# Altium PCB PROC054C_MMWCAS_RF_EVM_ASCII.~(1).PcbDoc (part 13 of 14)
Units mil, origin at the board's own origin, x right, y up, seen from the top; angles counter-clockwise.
Board outline 6299.21 x 5370.07 mil, 8 copper layers (L1 TOP, L2 GND, L3 SIGNAL 1, L4 GND, L5 SIGNAL 2, L6 SIGNAL 3, L7 GND, L8 BOTTOM), stack 53.5 mil thick; 775 components, 552 nets, 2648 pads, 7845 vias.
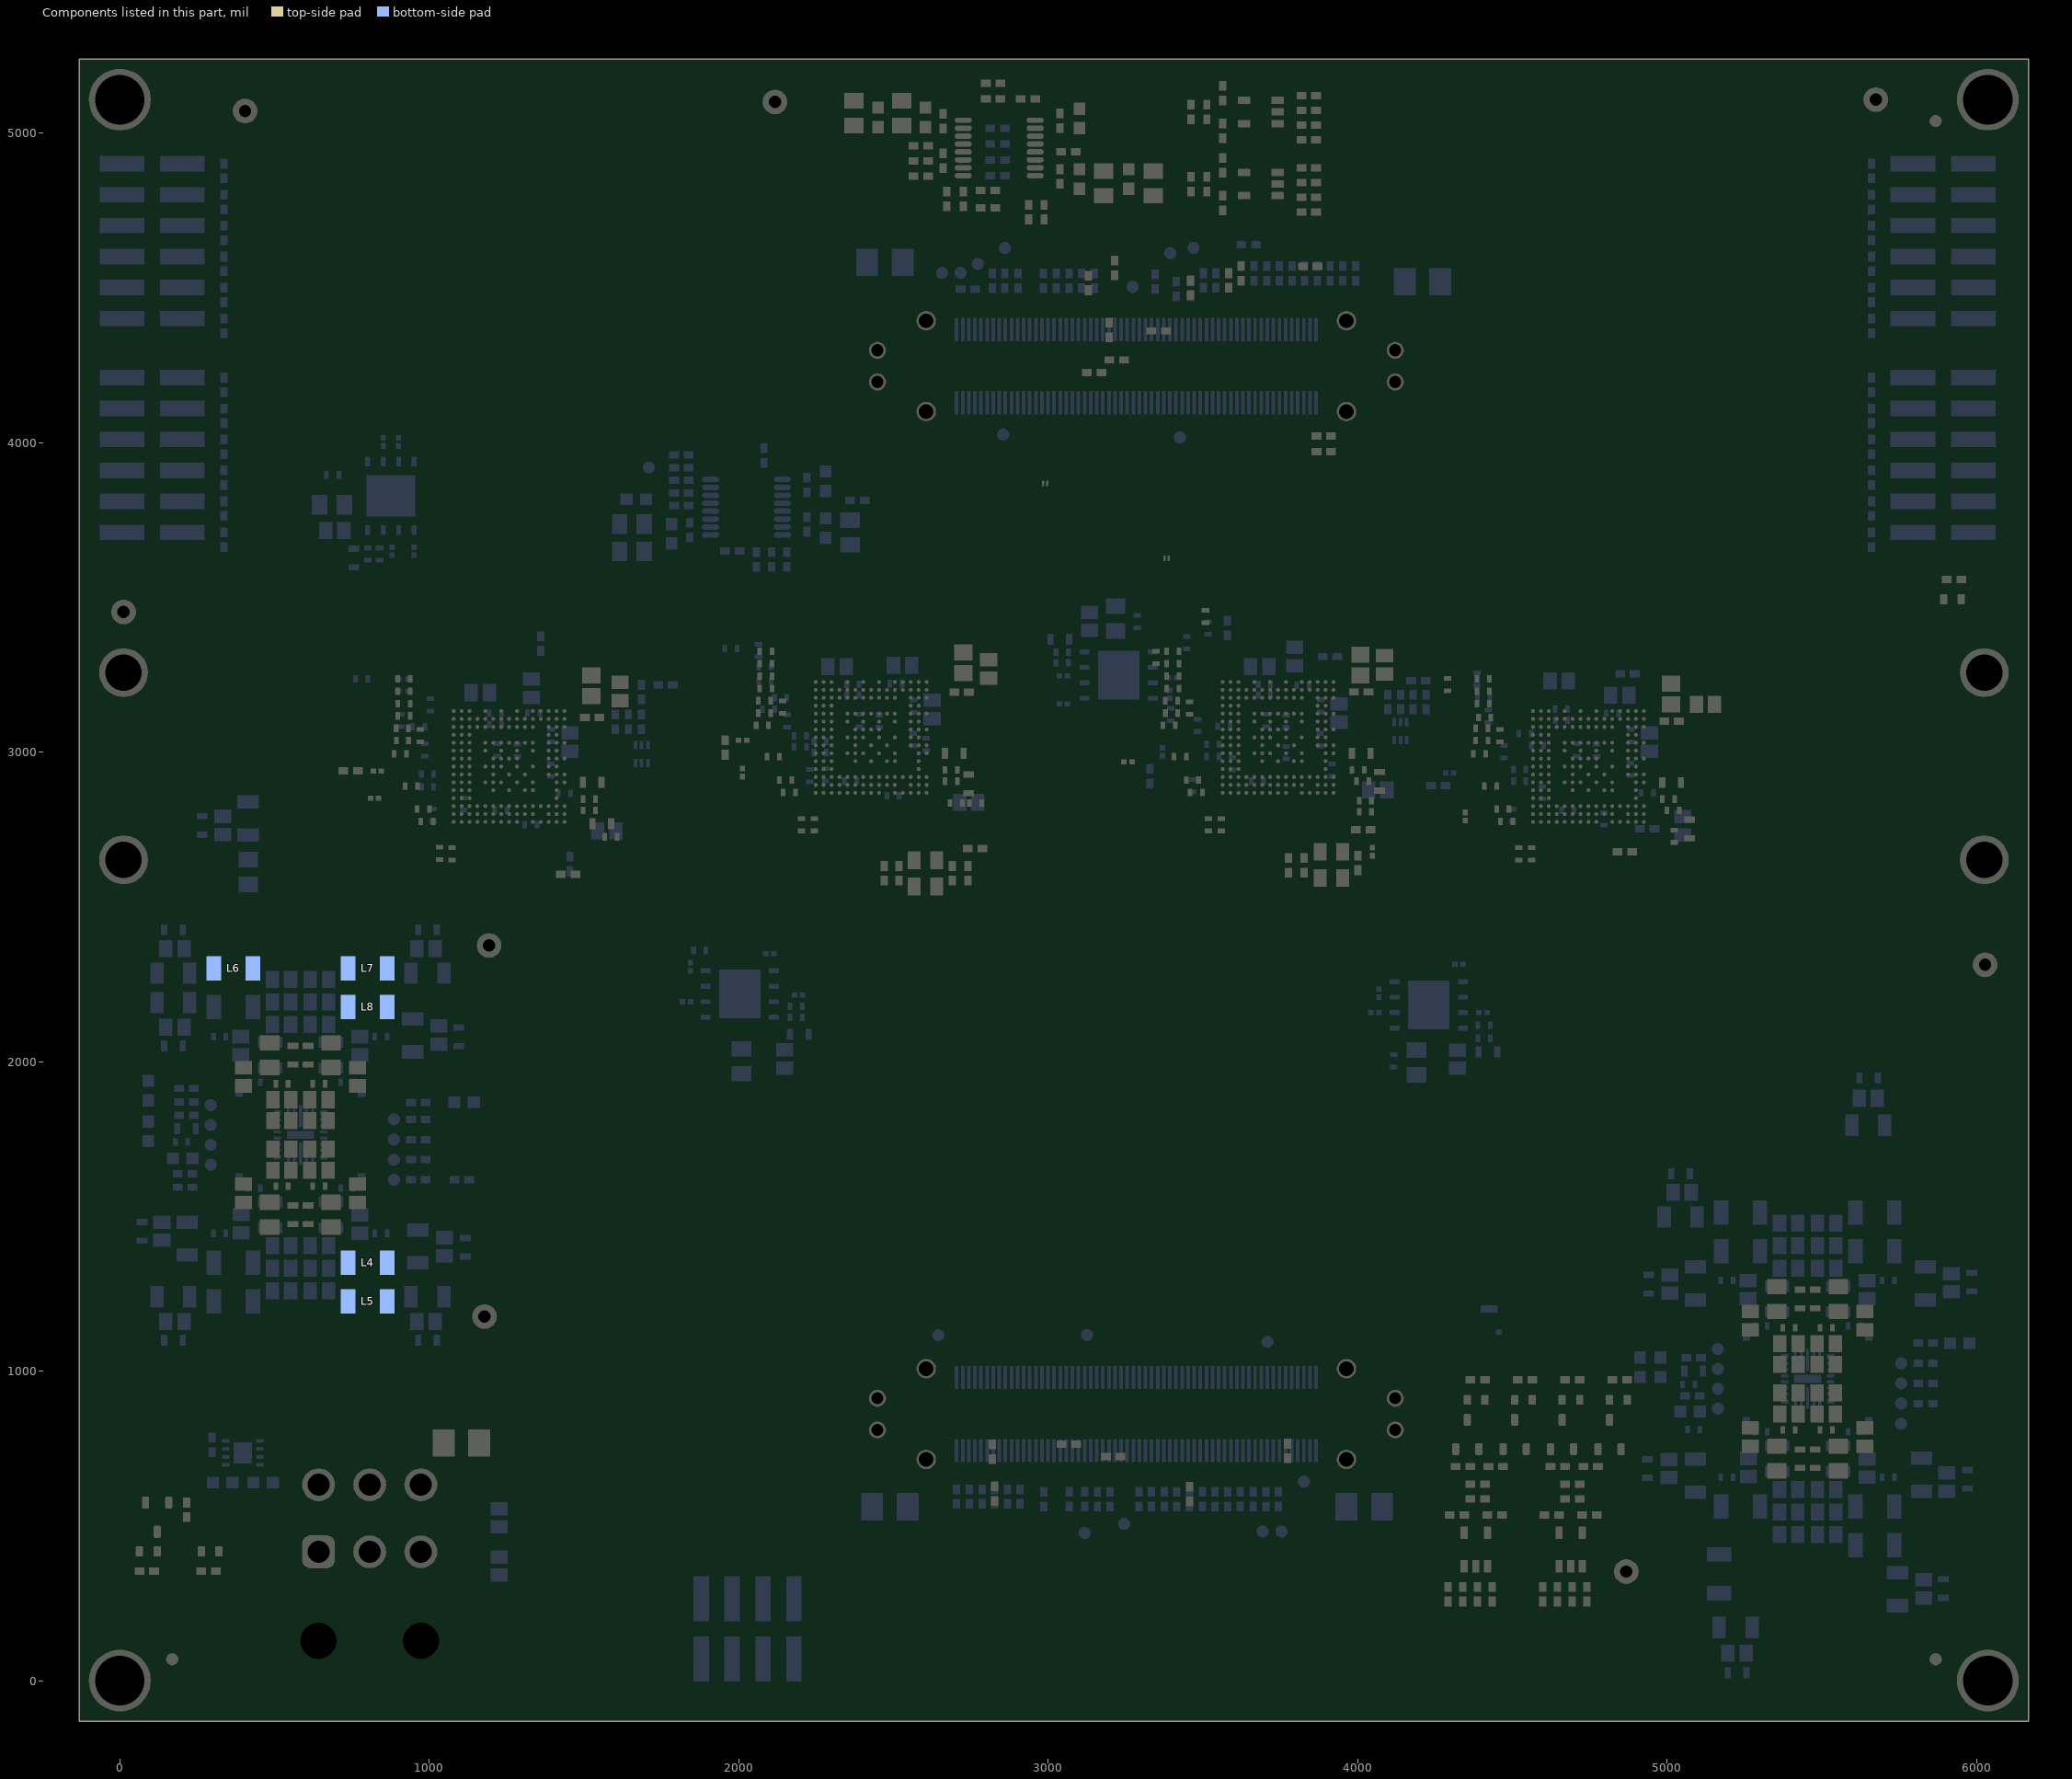
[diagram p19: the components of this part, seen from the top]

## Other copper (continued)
L4 GND:
  region net 12XX_1_1V0_RF2_FILT: 2620.92,3259.25 2665.33,3259.25 2670.56,3254.02 2670.56,3226.92 2665.38,3221.74 2638.48,3221.74 2633.14,3227.07 2633.14,3239.54 2631.24,3241.45 2618.47,3241.45 2613.33,3246.59 2613.33,3251.44
  region net SYSTEM_5V0: 2515.39,514.41 2579.92,514.41 2585.03,509.31 2585.03,461.62 2579.6,456.18 2512.89,456.18 2507.35,461.73 2507.35,508.77 2513,514.41 2515.32,514.41
  region net 12XX_1_1V8_FILT: 2509.9,3360.96 2509.9,3384.51 2515.63,3390.24 2515.63,3402.55 2526.45,3413.37 2526.45,3418.78 2532.18,3424.51 2537.8,3424.51 2543.21,3419.1 2543.21,3410.19 2535.36,3402.34 2535.36,3398.41 2526.77,3389.82 2526.77,3375.28 2525.18,3373.69 2525.18,3361.59 2519.87,3356.29
  region net 12XX_1_1V0_RF1_FILT: 2242.48,3438.84 2253.42,3427.91 2253.42,3403.17 2258.55,3398.04 2285.85,3398.04 2291.36,3403.54 2291.36,3430.62 2286.08,3435.9 2264.2,3435.9 2260.58,3439.52 2260.58,3446.84 2255.3,3452.12 2247.64,3452.12 2242.48,3446.96
  region net SYSTEM_3V3: 4845.85,289.56 4894.85,289.56 4900.29,284.12 4900.29,255.7 4894.37,249.77 4846.56,249.77 4840.64,255.7 4840.64,284.36 4845.84,289.55
  region net 12XX_1_1V0_RF1_FILT: 1146.34,1308.09 1152.4,1302.04 1179.47,1302.04 1186.13,1308.64 1186.13,1374.29 1180.2,1380.21 1151.78,1380.21 1146.34,1374.77
  region net 12XX_1_1V2_FILT: 250.75,1173.19 244.84,1167.28 244.84,1120.13 251.44,1113.54 296.41,1113.54 303.01,1120.13 303.01,1166.96 296.78,1173.19
  region net 12XX_4_1V2_FILT: 158.43,1351.31 164.02,1356.9 164.02,1385.06 157.98,1391.1 72,1391.1 66.08,1385.18 66.08,1356.76 71.53,1351.31
  region net 12XX_1_1V8_FILT: 234.22,2041.49 239.81,2035.9 267.97,2035.9 274.01,2041.94 274.01,2127.92 268.09,2133.84 239.67,2133.84 234.22,2128.39
  region net 12XX_4_1V8_FILT: 250.75,2411.83 244.84,2405.92 244.84,2358.78 251.44,2352.18 296.41,2352.18 303.01,2358.78 303.01,2405.6 296.78,2411.83
  region net SYSTEM_1V8: 307.86,2641.07 307.86,2690.07 313.3,2695.51 341.72,2695.51 347.65,2689.59 347.65,2641.78 341.72,2635.86 313.06,2635.86 307.87,2641.06
  region net 12XX_4_1V2_FILT: -21.09,2941.66 -15.5,2936.08 12.66,2936.08 18.7,2942.12 18.7,3028.09 12.78,3034.02 -15.64,3034.02 -21.09,3028.57
  region net SYSTEM_1V8: 662.48,4740.5 662.48,4789.5 667.93,4794.94 696.35,4794.94 702.27,4789.02 702.27,4741.22 696.35,4735.29 667.69,4735.29 662.49,4740.49
  region net GND: 2389.91,4689.37 2384.62,4684.08 2384.9,4683.8 2384.9,4635.9 2391.08,4629.72 2437.22,4629.72 2443.65,4636.15 2443.65,4684.1 2438.39,4689.37
  region net SYSTEM_5V0: 2503.12,4689.87 2497.84,4684.58 2498.12,4684.3 2498.12,4636.39 2504.3,4630.22 2550.43,4630.22 2556.87,4636.65 2556.87,4684.6 2551.6,4689.87
  region net SYSTEM_5V0: 4128.16,4421 4122.87,4415.71 4123.16,4415.43 4123.16,4367.52 4129.33,4361.35 4175.47,4361.35 4181.9,4367.78 4181.9,4415.73 4176.64,4421
  region net SYSTEM_3V3: 5428.5,5134.79 5423.08,5140.21 5375.13,5140.21 5369.76,5134.91 5369.76,5105.96 5375.02,5100.7 5423.5,5100.7 5428.78,5105.99 5428.5,5106.27
  region net 12XX_2_1V0_RF1_FILT: 4785.96,3522.44 4780.54,3527.86 4732.59,3527.86 4727.22,3522.56 4727.22,3493.62 4732.48,3488.36 4780.96,3488.36 4786.25,3493.64 4785.96,3493.93
  region net 12XX_2_1V0_RF2_FILT: 5238.93,2890.61 5244.61,2884.92 5272.41,2884.92 5278.44,2890.95 5278.44,2957.75 5273.13,2963.12 5244.19,2963.12 5238.93,2957.86
  region net 12XX_2_1V0_RF1_FILT: 5530.8,2067.9 5525.52,2062.62 5525.8,2062.33 5525.8,2014.43 5531.98,2008.25 5578.11,2008.25 5584.55,2014.69 5584.55,2062.64 5579.28,2067.9
  region net PMIC2_VIN_B3: 5338.43,1070.07 5333.25,1064.89 5287.55,1064.89 5282.54,1069.9 5282.54,1078.84 5324.94,1121.23 5332.95,1121.23 5338.43,1115.76
  region net PMIC2_VIN_B2: 5570.1,1070.07 5575.28,1064.89 5620.98,1064.89 5625.98,1069.9 5625.98,1078.84 5583.59,1121.23 5575.57,1121.23 5570.1,1115.76
  region net PMIC2_VIN_B0: 5570.1,880.14 5575.28,885.32 5620.98,885.32 5625.98,880.31 5625.98,871.38 5583.59,828.98 5575.57,828.98 5570.1,834.46
  region net PMIC2_VIN_B1: 5338.43,880.14 5333.25,885.32 5287.55,885.32 5282.54,880.31 5282.54,871.38 5324.94,828.98 5332.95,828.98 5338.43,834.46
  region net PMIC1_VIN_B3: 467.7,1857.93 462.53,1852.75 416.83,1852.75 411.82,1857.75 411.82,1866.69 454.22,1909.09 462.23,1909.09 467.7,1903.61
  region net PMIC1_VIN_B2: 699.37,1857.93 704.55,1852.75 750.25,1852.75 755.26,1857.75 755.26,1866.69 712.86,1909.09 704.85,1909.09 699.37,1903.61
  region net PMIC1_VIN_B0: 699.37,1668 704.55,1673.18 750.25,1673.18 755.26,1668.17 755.26,1659.23 712.86,1616.84 704.85,1616.84 699.37,1622.31
  region net PMIC1_VIN_B1: 467.7,1668 462.53,1673.18 416.83,1673.18 411.82,1668.17 411.82,1659.23 454.22,1616.84 462.23,1616.84 467.7,1622.31
  region net 12XX_2_1V0_RF1_FILT: 5805.08,436.36 5799.8,431.08 5800.08,430.8 5800.08,382.89 5806.26,376.72 5852.39,376.72 5858.82,383.15 5858.82,431.1 5853.56,436.36
  region net 12XX_2_1V0_RF2_FILT: 5774.35,579.38 5769.06,574.1 5769.34,573.81 5769.34,525.91 5775.52,519.73 5821.66,519.73 5828.09,526.16 5828.09,574.12 5822.82,579.38
  region net 12XX_1_1V0_RF2_FILT: 2761.15,1302.47 2761.15,1284.2 2767.54,1277.81 2794.49,1277.81 2800.93,1284.25 2800.93,1351 2795.01,1356.92 2766.59,1356.92 2761.14,1351.48 2761.14,1302.48
  region net 12XX_2_1V2_FILT: 4755.72,1315.7 4750.43,1310.42 4750.71,1310.13 4750.71,1262.23 4756.89,1256.05 4803.03,1256.05 4809.46,1262.48 4809.46,1310.44 4804.19,1315.7
  region net 12XX_3_1V8_FILT: 4929.6,1404.03 4924.32,1398.74 4924.6,1398.46 4924.6,1350.56 4930.78,1344.38 4976.91,1344.38 4983.34,1350.81 4983.34,1398.77 4978.08,1404.03
  region net SYSTEM_5V0: 3939.25,650.91 3988.25,650.91 3993.69,645.46 3993.69,617.04 3987.77,611.12 3939.96,611.12 3934.04,617.04 3934.04,645.7 3939.24,650.9
  region net SYSTEM_5V0: 3938.79,510.36 3987.79,510.36 3993.24,504.92 3993.24,476.5 3987.32,470.57 3939.51,470.57 3933.59,476.5 3933.59,505.16 3938.79,510.35
  region net GND: 4119.13,512.68 4123.93,507.89 4123.93,437.77 4118.78,432.62 4050.85,432.62 4043.44,440.03 4043.44,505.72 4050.4,512.68
  region net 12XX_3_1V2_FILT: 3927.84,1110.58 3933.19,1115.94 3982.82,1115.94 3987.48,1111.28 3987.48,1062.72 3981.35,1056.58 3934.18,1056.58 3927.84,1062.92
  region net 12XX_1_1V0_RF2_FILT: 1496.65,721.57 1496.65,676.41 1497.73,675.32 1504.94,668.12 1552.12,668.12 1558.09,674.09 1558.09,723.96 1553.52,728.53 1503.61,728.53
  pour cut-out: 1317.77,2696.74 1317.77,2690.42 1329.87,2690.53 1329.87,2711.78 1324,2711.78
  pour cut-out: 2192.66,2682.81 2186.34,2682.81 2186.45,2670.7 2207.7,2670.7 2207.7,2676.58
  pour cut-out: 2464.68,2700.17 2458.36,2700.17 2458.47,2688.06 2479.72,2688.06 2479.72,2693.94
  pour cut-out: 4510.66,2588.93 4504.34,2588.93 4504.45,2576.83 4525.7,2576.83 4525.7,2582.7
  region net SYSTEM_3V3: 215.58,674.66 215.58,627.6 222.37,620.82 269.86,620.82 274.57,625.52 274.57,676.3 270.08,680.79 221.71,680.79
  text "4" at 1249.65,7.05 h65
  text ".Layer_Name" at 445.07,-990.08 h60
L5 SIGNAL 2:
  region net 12XX_1_1V0_RF2_FILT: 2620.92,3259.25 2665.33,3259.25 2670.56,3254.02 2670.56,3226.92 2665.38,3221.74 2638.48,3221.74 2633.14,3227.07 2633.14,3239.54 2631.24,3241.45 2618.47,3241.45 2613.33,3246.59 2613.33,3251.44
  region net SYSTEM_5V0: 2515.39,514.41 2579.92,514.41 2585.03,509.31 2585.03,461.62 2579.6,456.18 2512.89,456.18 2507.35,461.73 2507.35,508.77 2513,514.41 2515.32,514.41
  region net 12XX_1_1V8_FILT: 2509.9,3360.96 2509.9,3384.51 2515.63,3390.24 2515.63,3402.55 2526.45,3413.37 2526.45,3418.78 2532.18,3424.51 2537.8,3424.51 2543.21,3419.1 2543.21,3410.19 2535.36,3402.34 2535.36,3398.41 2526.77,3389.82 2526.77,3375.28 2525.18,3373.69 2525.18,3361.59 2519.87,3356.29
  region net 12XX_1_1V2_FILT: 250.75,1173.19 244.84,1167.28 244.84,1120.13 251.44,1113.54 296.41,1113.54 303.01,1120.13 303.01,1166.96 296.78,1173.19
  region net 12XX_4_1V2_FILT: 158.43,1351.31 164.02,1356.9 164.02,1385.06 157.98,1391.1 72,1391.1 66.08,1385.18 66.08,1356.76 71.53,1351.31
  region net 12XX_1_1V8_FILT: 234.22,2041.49 239.81,2035.9 267.97,2035.9 274.01,2041.94 274.01,2127.92 268.09,2133.84 239.67,2133.84 234.22,2128.39
  region net 12XX_4_1V8_FILT: 250.75,2411.83 244.84,2405.92 244.84,2358.78 251.44,2352.18 296.41,2352.18 303.01,2358.78 303.01,2405.6 296.78,2411.83
  region net SYSTEM_1V8: 307.86,2641.07 307.86,2690.07 313.3,2695.51 341.72,2695.51 347.65,2689.59 347.65,2641.78 341.72,2635.86 313.06,2635.86 307.87,2641.06
  region net 12XX_4_1V2_FILT: -21.09,2941.66 -15.5,2936.08 12.66,2936.08 18.7,2942.12 18.7,3028.09 12.78,3034.02 -15.64,3034.02 -21.09,3028.57
  region net SYSTEM_1V8: 662.48,4740.5 662.48,4789.5 667.93,4794.94 696.35,4794.94 702.27,4789.02 702.27,4741.22 696.35,4735.29 667.69,4735.29 662.49,4740.49
  region net GND: 2389.91,4689.37 2384.62,4684.08 2384.9,4683.8 2384.9,4635.9 2391.08,4629.72 2437.22,4629.72 2443.65,4636.15 2443.65,4684.1 2438.39,4689.37
  region net SYSTEM_5V0: 2503.12,4689.87 2497.84,4684.58 2498.12,4684.3 2498.12,4636.39 2504.3,4630.22 2550.43,4630.22 2556.87,4636.65 2556.87,4684.6 2551.6,4689.87
  region net SYSTEM_5V0: 4128.16,4421 4122.87,4415.71 4123.16,4415.43 4123.16,4367.52 4129.33,4361.35 4175.47,4361.35 4181.9,4367.78 4181.9,4415.73 4176.64,4421
  region net PMIC2_VIN_B3: 5338.43,1070.07 5333.25,1064.89 5287.55,1064.89 5282.54,1069.9 5282.54,1078.84 5324.94,1121.23 5332.95,1121.23 5338.43,1115.76
  region net PMIC2_VIN_B2: 5570.1,1070.07 5575.28,1064.89 5620.98,1064.89 5625.98,1069.9 5625.98,1078.84 5583.59,1121.23 5575.57,1121.23 5570.1,1115.76
  region net PMIC2_VIN_B0: 5570.1,880.14 5575.28,885.32 5620.98,885.32 5625.98,880.31 5625.98,871.38 5583.59,828.98 5575.57,828.98 5570.1,834.46
  region net PMIC2_VIN_B1: 5338.43,880.14 5333.25,885.32 5287.55,885.32 5282.54,880.31 5282.54,871.38 5324.94,828.98 5332.95,828.98 5338.43,834.46
  region net PMIC1_VIN_B3: 467.7,1857.93 462.53,1852.75 416.83,1852.75 411.82,1857.75 411.82,1866.69 454.22,1909.09 462.23,1909.09 467.7,1903.61
  region net PMIC1_VIN_B2: 699.37,1857.93 704.55,1852.75 750.25,1852.75 755.26,1857.75 755.26,1866.69 712.86,1909.09 704.85,1909.09 699.37,1903.61
  region net PMIC1_VIN_B0: 699.37,1668 704.55,1673.18 750.25,1673.18 755.26,1668.17 755.26,1659.23 712.86,1616.84 704.85,1616.84 699.37,1622.31
  region net PMIC1_VIN_B1: 467.7,1668 462.53,1673.18 416.83,1673.18 411.82,1668.17 411.82,1659.23 454.22,1616.84 462.23,1616.84 467.7,1622.31
  region net GND: 5793,749.48 5798.42,744.06 5846.37,744.06 5851.74,749.36 5851.74,778.3 5846.48,783.56 5798,783.56 5792.71,778.28 5793,777.99
  region net 12XX_2_1V0_RF1_FILT: 5805.08,436.36 5799.8,431.08 5800.08,430.8 5800.08,382.89 5806.26,376.72 5852.39,376.72 5858.82,383.15 5858.82,431.1 5853.56,436.36
  region net 12XX_1_1V0_RF2_FILT: 2761.15,1302.47 2761.15,1284.2 2767.54,1277.81 2794.49,1277.81 2800.93,1284.25 2800.93,1351 2795.01,1356.92 2766.59,1356.92 2761.14,1351.48 2761.14,1302.48
  region net 12XX_2_1V2_FILT: 4755.72,1315.7 4750.43,1310.42 4750.71,1310.13 4750.71,1262.23 4756.89,1256.05 4803.03,1256.05 4809.46,1262.48 4809.46,1310.44 4804.19,1315.7
  region net 12XX_3_1V8_FILT: 4929.6,1404.03 4924.32,1398.74 4924.6,1398.46 4924.6,1350.56 4930.78,1344.38 4976.91,1344.38 4983.34,1350.81 4983.34,1398.77 4978.08,1404.03
  region net SYSTEM_5V0: 3939.25,650.91 3988.25,650.91 3993.69,645.46 3993.69,617.04 3987.77,611.12 3939.96,611.12 3934.04,617.04 3934.04,645.7 3939.24,650.9
  region net SYSTEM_5V0: 3938.79,510.36 3987.79,510.36 3993.24,504.92 3993.24,476.5 3987.32,470.57 3939.51,470.57 3933.59,476.5 3933.59,505.16 3938.79,510.35
  region net GND: 4119.13,512.68 4123.93,507.89 4123.93,437.77 4118.78,432.62 4050.85,432.62 4043.44,440.03 4043.44,505.72 4050.4,512.68
  region net 12XX_3_1V2_FILT: 3927.84,1110.58 3933.19,1115.94 3982.82,1115.94 3987.48,1111.28 3987.48,1062.72 3981.35,1056.58 3934.18,1056.58 3927.84,1062.92
  region net 12XX_1_1V0_RF2_FILT: 1496.65,721.57 1496.65,676.41 1497.73,675.32 1504.94,668.12 1552.12,668.12 1558.09,674.09 1558.09,723.96 1553.52,728.53 1503.61,728.53
  pour cut-out: 414.57,1126.88 414.57,1043.88 753.57,1043.88 753.57,1126.88
  region net GND: 5191.77,1156.41 5191.77,1118.51 5235.66,1074.61 5254.42,1074.61 5260.41,1080.6 5260.41,1137.89 5237.16,1161.14 5196.5,1161.14 5191.77,1156.41
  region net GND: 5716.76,1156.41 5716.76,1118.51 5672.86,1074.61 5654.11,1074.61 5648.11,1080.6 5648.11,1137.89 5671.36,1161.14 5712.03,1161.14 5716.75,1156.41
  region net GND: 5191.77,793.81 5191.77,831.71 5235.66,875.6 5254.42,875.6 5260.41,869.61 5260.41,812.33 5237.16,789.07 5196.5,789.07 5191.77,793.8
  region net GND: 5694.62,799.08 5694.63,860.05 5679.07,875.6 5654.11,875.6 5644.92,866.42 5644.92,822.29 5674.44,792.77 5688.3,792.77
  region net GND: 5434.21,1071.1 5441.91,1063.4 5466.2,1063.4 5473.9,1071.1 5473.9,1113.59 5499.23,1138.92 5499.23,1196.56 5511.8,1209.13 5622.3,1209.13 5629.68,1216.51 5629.68,1242.04 5615.72,1256 5290.2,1256 5273.64,1239.45 5273.64,1223.69 5286.61,1210.72 5392.52,1210.72 5408.48,1194.77 5408.48,1137.52 5434.21,1111.79
  region net GND: 5434.21,879.11 5441.91,886.81 5466.2,886.81 5473.9,879.11 5473.9,836.63 5499.23,811.3 5499.23,753.65 5511.8,741.08 5622.3,741.08 5629.68,733.7 5629.68,708.17 5615.72,694.21 5290.2,694.21 5273.64,710.77 5273.64,726.52 5286.61,739.49 5392.52,739.49 5408.48,755.45 5408.48,812.69 5434.21,838.42
  region net GND: 321.04,1944.26 321.04,1906.36 364.94,1862.47 383.69,1862.47 389.69,1868.46 389.69,1925.74 366.44,1948.99 325.77,1948.99 321.05,1944.27
  region net GND: 846.03,1944.26 846.03,1906.36 802.14,1862.47 783.38,1862.47 777.39,1868.46 777.39,1925.74 800.64,1948.99 841.3,1948.99 846.03,1944.27
  region net GND: 321.04,1581.66 321.04,1619.56 364.94,1663.46 383.69,1663.46 389.69,1657.46 389.69,1600.18 366.44,1576.93 325.77,1576.93 321.05,1581.66
  region net GND: 823.89,1586.94 823.9,1647.9 808.34,1663.46 783.38,1663.46 774.2,1654.27 774.2,1610.14 803.71,1580.62 817.58,1580.62
  region net GND: 563.48,1858.96 571.18,1851.26 595.48,1851.26 603.18,1858.96 603.18,1901.44 628.51,1926.77 628.51,1984.42 641.07,1996.98 751.58,1996.98 758.96,2004.36 758.96,2029.9 745,2043.86 419.47,2043.86 402.92,2027.3 402.92,2011.54 415.88,1998.58 521.8,1998.58 537.75,1982.62 537.75,1925.38 563.48,1899.65
  region net GND: 563.48,1666.97 571.18,1674.67 595.48,1674.67 603.18,1666.97 603.18,1624.48 628.51,1599.15 628.51,1541.51 641.07,1528.94 751.58,1528.94 758.96,1521.56 758.96,1496.03 745,1482.07 419.47,1482.07 402.92,1498.62 402.92,1514.38 415.88,1527.34 521.8,1527.34 537.75,1543.3 537.75,1600.55 563.48,1626.28
  pour cut-out: 1154.65,2394.48 1154.65,2355.29 1173.45,2336.49 1211.96,2336.49 1211.96,2340.12 1229.62,2357.78 1229.62,2392.89 1205.62,2416.9 1176.17,2416.9 1170.96,2411.69
  pour cut-out: 1317.77,2696.74 1317.77,2690.42 1329.87,2690.53 1329.87,2711.78 1324,2711.78
  pour cut-out: 2192.66,2682.81 2186.34,2682.81 2186.45,2670.7 2207.7,2670.7 2207.7,2676.58
  pour cut-out: 2464.68,2700.17 2458.36,2700.17 2458.47,2688.06 2479.72,2688.06 2479.72,2693.94
  pour cut-out: 4510.66,2588.93 4504.34,2588.93 4504.45,2576.83 4525.7,2576.83 4525.7,2582.7
  text "5" at 1250.92,5.78 h65
  text ".Layer_Name" at 445.07,-990.08 h60
L6 SIGNAL 3:
  region net 12XX_1_1V0_RF1_FILT: 2242.48,3438.84 2253.42,3427.91 2253.42,3403.17 2258.55,3398.04 2285.85,3398.04 2291.36,3403.54 2291.36,3430.62 2286.08,3435.9 2264.2,3435.9 2260.58,3439.52 2260.58,3446.84 2255.3,3452.12 2247.64,3452.12 2242.48,3446.96
  region net SYSTEM_3V3: 4845.85,289.56 4894.85,289.56 4900.29,284.12 4900.29,255.7 4894.37,249.77 4846.56,249.77 4840.64,255.7 4840.64,284.36 4845.84,289.55
  region net 12XX_1_1V0_RF1_FILT: 1146.34,1308.09 1152.4,1302.04 1179.47,1302.04 1186.13,1308.64 1186.13,1374.29 1180.2,1380.21 1151.78,1380.21 1146.34,1374.77
  region net 12XX_1_1V2_FILT: 250.75,1173.19 244.84,1167.28 244.84,1120.13 251.44,1113.54 296.41,1113.54 303.01,1120.13 303.01,1166.96 296.78,1173.19
  region net 12XX_4_1V2_FILT: 158.43,1351.31 164.02,1356.9 164.02,1385.06 157.98,1391.1 72,1391.1 66.08,1385.18 66.08,1356.76 71.53,1351.31
  region net 12XX_1_1V8_FILT: 234.22,2041.49 239.81,2035.9 267.97,2035.9 274.01,2041.94 274.01,2127.92 268.09,2133.84 239.67,2133.84 234.22,2128.39
  region net 12XX_4_1V8_FILT: 250.75,2411.83 244.84,2405.92 244.84,2358.78 251.44,2352.18 296.41,2352.18 303.01,2358.78 303.01,2405.6 296.78,2411.83
  region net 12XX_4_1V2_FILT: -21.09,2941.66 -15.5,2936.08 12.66,2936.08 18.7,2942.12 18.7,3028.09 12.78,3034.02 -15.64,3034.02 -21.09,3028.57
  region net GND: 2389.91,4689.37 2384.62,4684.08 2384.9,4683.8 2384.9,4635.9 2391.08,4629.72 2437.22,4629.72 2443.65,4636.15 2443.65,4684.1 2438.39,4689.37
  region net SYSTEM_5V0: 2503.12,4689.87 2497.84,4684.58 2498.12,4684.3 2498.12,4636.39 2504.3,4630.22 2550.43,4630.22 2556.87,4636.65 2556.87,4684.6 2551.6,4689.87
  region net GND: 4298.52,4628.49 4304,4623 4304,4575.03 4297.81,4568.84 4232.2,4568.84 4225.74,4575.3 4225.74,4623.2 4231.02,4628.49
  region net SYSTEM_5V0: 4128.16,4421 4122.87,4415.71 4123.16,4415.43 4123.16,4367.52 4129.33,4361.35 4175.47,4361.35 4181.9,4367.78 4181.9,4415.73 4176.64,4421
  region net SYSTEM_3V3: 5428.5,5134.79 5423.08,5140.21 5375.13,5140.21 5369.76,5134.91 5369.76,5105.96 5375.02,5100.7 5423.5,5100.7 5428.78,5105.99 5428.5,5106.27
  region net 12XX_2_1V0_RF1_FILT: 4785.96,3522.44 4780.54,3527.86 4732.59,3527.86 4727.22,3522.56 4727.22,3493.62 4732.48,3488.36 4780.96,3488.36 4786.25,3493.64 4785.96,3493.93
  region net 12XX_2_1V0_RF2_FILT: 5238.93,2890.61 5244.61,2884.92 5272.41,2884.92 5278.44,2890.95 5278.44,2957.75 5273.13,2963.12 5244.19,2963.12 5238.93,2957.86
  region net GND: 5792.46,1199.71 5797.89,1205.13 5797.89,1253.08 5792.58,1258.45 5763.64,1258.45 5758.38,1253.19 5758.38,1204.71 5763.66,1199.43 5763.95,1199.71
  region net 12XX_2_1V0_RF1_FILT: 5530.8,2067.9 5525.52,2062.62 5525.8,2062.33 5525.8,2014.43 5531.98,2008.25 5578.11,2008.25 5584.55,2014.69 5584.55,2062.64 5579.28,2067.9
  region net PMIC2_VIN_B3: 5338.43,1070.07 5333.25,1064.89 5287.55,1064.89 5282.54,1069.9 5282.54,1078.84 5324.94,1121.23 5332.95,1121.23 5338.43,1115.76
  region net PMIC2_VIN_B2: 5570.1,1070.07 5575.28,1064.89 5620.98,1064.89 5625.98,1069.9 5625.98,1078.84 5583.59,1121.23 5575.57,1121.23 5570.1,1115.76
  region net PMIC2_VIN_B0: 5570.1,880.14 5575.28,885.32 5620.98,885.32 5625.98,880.31 5625.98,871.38 5583.59,828.98 5575.57,828.98 5570.1,834.46
  region net PMIC2_VIN_B1: 5338.43,880.14 5333.25,885.32 5287.55,885.32 5282.54,880.31 5282.54,871.38 5324.94,828.98 5332.95,828.98 5338.43,834.46
  region net PMIC1_VIN_B3: 467.7,1857.93 462.53,1852.75 416.83,1852.75 411.82,1857.75 411.82,1866.69 454.22,1909.09 462.23,1909.09 467.7,1903.61
  region net PMIC1_VIN_B2: 699.37,1857.93 704.55,1852.75 750.25,1852.75 755.26,1857.75 755.26,1866.69 712.86,1909.09 704.85,1909.09 699.37,1903.61
  region net PMIC1_VIN_B0: 699.37,1668 704.55,1673.18 750.25,1673.18 755.26,1668.17 755.26,1659.23 712.86,1616.84 704.85,1616.84 699.37,1622.31
  region net PMIC1_VIN_B1: 467.7,1668 462.53,1673.18 416.83,1673.18 411.82,1668.17 411.82,1659.23 454.22,1616.84 462.23,1616.84 467.7,1622.31
  region net GND: 358.22,1523.9 361.4,1523.9 367.2,1518.09 367.2,1490.43 361.79,1485.02 334.16,1485.02 328.59,1490.59 328.59,1518.17 334.32,1523.91 357.48,1523.91
  region net GND: 829.54,1523.9 832.72,1523.9 838.53,1518.09 838.53,1490.43 833.11,1485.02 805.49,1485.02 799.92,1490.59 799.92,1518.17 805.65,1523.91 828.81,1523.91
  region net GND: 829.54,2041.06 832.72,2041.06 838.53,2035.26 838.53,2007.6 833.11,2002.19 805.49,2002.19 799.92,2007.76 799.92,2035.34 805.65,2041.07 828.81,2041.07
  region net GND: 358.22,2041.06 361.4,2041.06 367.2,2035.26 367.2,2007.6 361.79,2002.19 334.16,2002.19 328.59,2007.76 328.59,2035.34 334.32,2041.07 357.48,2041.07
  region net GND: 5228.94,736.04 5232.12,736.04 5237.92,730.24 5237.92,702.58 5232.51,697.17 5204.88,697.17 5199.32,702.74 5199.32,730.32 5205.05,736.05 5228.2,736.05
  region net GND: 5700.27,736.04 5703.45,736.04 5709.25,730.24 5709.25,702.58 5703.84,697.17 5676.21,697.17 5670.64,702.74 5670.64,730.32 5676.38,736.05 5699.53,736.05
  region net GND: 5700.27,1253.21 5703.45,1253.21 5709.25,1247.4 5709.25,1219.74 5703.84,1214.33 5676.21,1214.33 5670.64,1219.9 5670.64,1247.49 5676.38,1253.22 5699.53,1253.22
  region net GND: 5228.94,1253.21 5232.12,1253.21 5237.92,1247.4 5237.92,1219.74 5232.51,1214.33 5204.88,1214.33 5199.32,1219.9 5199.32,1247.49 5205.05,1253.22 5228.2,1253.22
  region net GND: 5793,749.48 5798.42,744.06 5846.37,744.06 5851.74,749.36 5851.74,778.3 5846.48,783.56 5798,783.56 5792.71,778.28 5793,777.99
  region net 12XX_2_1V0_RF1_FILT: 5805.08,436.36 5799.8,431.08 5800.08,430.8 5800.08,382.89 5806.26,376.72 5852.39,376.72 5858.82,383.15 5858.82,431.1 5853.56,436.36
  region net 12XX_2_1V0_RF2_FILT: 5774.35,579.38 5769.06,574.1 5769.34,573.81 5769.34,525.91 5775.52,519.73 5821.66,519.73 5828.09,526.16 5828.09,574.12 5822.82,579.38
  region net 12XX_1_1V0_RF2_FILT: 2761.15,1302.47 2761.15,1284.2 2767.54,1277.81 2794.49,1277.81 2800.93,1284.25 2800.93,1351 2795.01,1356.92 2766.59,1356.92 2761.14,1351.48 2761.14,1302.48
  region net 12XX_2_1V2_FILT: 4755.72,1315.7 4750.43,1310.42 4750.71,1310.13 4750.71,1262.23 4756.89,1256.05 4803.03,1256.05 4809.46,1262.48 4809.46,1310.44 4804.19,1315.7
  region net 12XX_3_1V8_FILT: 4929.6,1404.03 4924.32,1398.74 4924.6,1398.46 4924.6,1350.56 4930.78,1344.38 4976.91,1344.38 4983.34,1350.81 4983.34,1398.77 4978.08,1404.03
  region net SYSTEM_5V0: 3939.25,650.91 3988.25,650.91 3993.69,645.46 3993.69,617.04 3987.77,611.12 3939.96,611.12 3934.04,617.04 3934.04,645.7 3939.24,650.9
  region net SYSTEM_5V0: 3938.79,510.36 3987.79,510.36 3993.24,504.92 3993.24,476.5 3987.32,470.57 3939.51,470.57 3933.59,476.5 3933.59,505.16 3938.79,510.35
  region net GND: 4119.13,512.68 4123.93,507.89 4123.93,437.77 4118.78,432.62 4050.85,432.62 4043.44,440.03 4043.44,505.72 4050.4,512.68
  region net 12XX_3_1V2_FILT: 3927.84,1110.58 3933.19,1115.94 3982.82,1115.94 3987.48,1111.28 3987.48,1062.72 3981.35,1056.58 3934.18,1056.58 3927.84,1062.92
  region net GND: 2385.84,602.06 2390.64,597.26 2390.64,527.15 2385.49,522 2317.55,522 2310.15,529.4 2310.15,595.1 2317.11,602.06
  region net 12XX_1_1V0_RF2_FILT: 1496.65,721.57 1496.65,676.41 1497.73,675.32 1504.94,668.12 1552.12,668.12 1558.09,674.09 1558.09,723.96 1553.52,728.53 1503.61,728.53
  region net GND: 5191.77,1156.41 5191.77,1118.51 5235.66,1074.61 5254.42,1074.61 5260.41,1080.6 5260.41,1137.89 5237.16,1161.14 5196.5,1161.14 5191.77,1156.41
  region net GND: 5716.76,1156.41 5716.76,1118.51 5672.86,1074.61 5654.11,1074.61 5648.11,1080.6 5648.11,1137.89 5671.36,1161.14 5712.03,1161.14 5716.75,1156.41
  region net GND: 5191.77,793.81 5191.77,831.71 5235.66,875.6 5254.42,875.6 5260.41,869.61 5260.41,812.33 5237.16,789.07 5196.5,789.07 5191.77,793.8
  region net GND: 5694.62,799.08 5694.63,860.05 5679.07,875.6 5654.11,875.6 5644.92,866.42 5644.92,822.29 5674.44,792.77 5688.3,792.77
  region net GND: 5434.21,1071.1 5441.91,1063.4 5466.2,1063.4 5473.9,1071.1 5473.9,1113.59 5499.23,1138.92 5499.23,1196.56 5511.8,1209.13 5622.3,1209.13 5629.68,1216.51 5629.68,1242.04 5615.72,1256 5290.2,1256 5273.64,1239.45 5273.64,1223.69 5286.61,1210.72 5392.52,1210.72 5408.48,1194.77 5408.48,1137.52 5434.21,1111.79
  region net GND: 5434.21,879.11 5441.91,886.81 5466.2,886.81 5473.9,879.11 5473.9,836.63 5499.23,811.3 5499.23,753.65 5511.8,741.08 5622.3,741.08 5629.68,733.7 5629.68,708.17 5615.72,694.21 5290.2,694.21 5273.64,710.77 5273.64,726.52 5286.61,739.49 5392.52,739.49 5408.48,755.45 5408.48,812.69 5434.21,838.42
  region net GND: 321.04,1944.26 321.04,1906.36 364.94,1862.47 383.69,1862.47 389.69,1868.46 389.69,1925.74 366.44,1948.99 325.77,1948.99 321.05,1944.27
  region net GND: 846.03,1944.26 846.03,1906.36 802.14,1862.47 783.38,1862.47 777.39,1868.46 777.39,1925.74 800.64,1948.99 841.3,1948.99 846.03,1944.27
  region net GND: 321.04,1581.66 321.04,1619.56 364.94,1663.46 383.69,1663.46 389.69,1657.46 389.69,1600.18 366.44,1576.93 325.77,1576.93 321.05,1581.66
  region net GND: 823.89,1586.94 823.9,1647.9 808.34,1663.46 783.38,1663.46 774.2,1654.27 774.2,1610.14 803.71,1580.62 817.58,1580.62
  region net GND: 563.48,1858.96 571.18,1851.26 595.48,1851.26 603.18,1858.96 603.18,1901.44 628.51,1926.77 628.51,1984.42 641.07,1996.98 751.58,1996.98 758.96,2004.36 758.96,2029.9 745,2043.86 419.47,2043.86 402.92,2027.3 402.92,2011.54 415.88,1998.58 521.8,1998.58 537.75,1982.62 537.75,1925.38 563.48,1899.65
  region net GND: 563.48,1666.97 571.18,1674.67 595.48,1674.67 603.18,1666.97 603.18,1624.48 628.51,1599.15 628.51,1541.51 641.07,1528.94 751.58,1528.94 758.96,1521.56 758.96,1496.03 745,1482.07 419.47,1482.07 402.92,1498.62 402.92,1514.38 415.88,1527.34 521.8,1527.34 537.75,1543.3 537.75,1600.55 563.48,1626.28
  pour cut-out: 5190.73,1216.47 5240.4,1166.8 5240.4,783.76 5190.76,734.11 5190.76,698.93 5201.13,688.55 5707.18,688.55 5717.89,699.27 5717.89,733.99 5668.25,783.63 5668.25,1166.58 5717.88,1216.21 5717.88,1251.17 5707.39,1261.66 5201.13,1261.66 5190.73,1251.25
  region net SYSTEM_3V3: 215.58,674.66 215.58,627.6 222.37,620.82 269.86,620.82 274.57,625.52 274.57,676.3 270.08,680.79 221.71,680.79
  text "6" at 1253.03,7.89 h65
  text ".Layer_Name" at 445.07,-990.08 h60
L7 GND:
  region net 12XX_1_1V0_RF2_FILT: 2620.92,3259.25 2665.33,3259.25 2670.56,3254.02 2670.56,3226.92 2665.38,3221.74 2638.48,3221.74 2633.14,3227.07 2633.14,3239.54 2631.24,3241.45 2618.47,3241.45 2613.33,3246.59 2613.33,3251.44
  region net SYSTEM_5V0: 2515.39,514.41 2579.92,514.41 2585.03,509.31 2585.03,461.62 2579.6,456.18 2512.89,456.18 2507.35,461.73 2507.35,508.77 2513,514.41 2515.32,514.41
  region net 12XX_1_1V8_FILT: 2509.9,3360.96 2509.9,3384.51 2515.63,3390.24 2515.63,3402.55 2526.45,3413.37 2526.45,3418.78 2532.18,3424.51 2537.8,3424.51 2543.21,3419.1 2543.21,3410.19 2535.36,3402.34 2535.36,3398.41 2526.77,3389.82 2526.77,3375.28 2525.18,3373.69 2525.18,3361.59 2519.87,3356.29
  region net 12XX_1_1V0_RF1_FILT: 2242.48,3438.84 2253.42,3427.91 2253.42,3403.17 2258.55,3398.04 2285.85,3398.04 2291.36,3403.54 2291.36,3430.62 2286.08,3435.9 2264.2,3435.9 2260.58,3439.52 2260.58,3446.84 2255.3,3452.12 2247.64,3452.12 2242.48,3446.96
  region net SYSTEM_3V3: 4845.85,289.56 4894.85,289.56 4900.29,284.12 4900.29,255.7 4894.37,249.77 4846.56,249.77 4840.64,255.7 4840.64,284.36 4845.84,289.55
  region net 12XX_1_1V0_RF1_FILT: 1146.34,1308.09 1152.4,1302.04 1179.47,1302.04 1186.13,1308.64 1186.13,1374.29 1180.2,1380.21 1151.78,1380.21 1146.34,1374.77
  region net 12XX_1_1V2_FILT: 250.75,1173.19 244.84,1167.28 244.84,1120.13 251.44,1113.54 296.41,1113.54 303.01,1120.13 303.01,1166.96 296.78,1173.19
  region net 12XX_4_1V2_FILT: 158.43,1351.31 164.02,1356.9 164.02,1385.06 157.98,1391.1 72,1391.1 66.08,1385.18 66.08,1356.76 71.53,1351.31
  region net 12XX_1_1V8_FILT: 234.22,2041.49 239.81,2035.9 267.97,2035.9 274.01,2041.94 274.01,2127.92 268.09,2133.84 239.67,2133.84 234.22,2128.39
  region net 12XX_4_1V8_FILT: 250.75,2411.83 244.84,2405.92 244.84,2358.78 251.44,2352.18 296.41,2352.18 303.01,2358.78 303.01,2405.6 296.78,2411.83
  region net SYSTEM_1V8: 307.86,2641.07 307.86,2690.07 313.3,2695.51 341.72,2695.51 347.65,2689.59 347.65,2641.78 341.72,2635.86 313.06,2635.86 307.87,2641.06
  region net 12XX_4_1V2_FILT: -21.09,2941.66 -15.5,2936.08 12.66,2936.08 18.7,2942.12 18.7,3028.09 12.78,3034.02 -15.64,3034.02 -21.09,3028.57
  region net SYSTEM_1V8: 662.48,4740.5 662.48,4789.5 667.93,4794.94 696.35,4794.94 702.27,4789.02 702.27,4741.22 696.35,4735.29 667.69,4735.29 662.49,4740.49
  region net GND: 2389.91,4689.37 2384.62,4684.08 2384.9,4683.8 2384.9,4635.9 2391.08,4629.72 2437.22,4629.72 2443.65,4636.15 2443.65,4684.1 2438.39,4689.37
  region net SYSTEM_5V0: 2503.12,4689.87 2497.84,4684.58 2498.12,4684.3 2498.12,4636.39 2504.3,4630.22 2550.43,4630.22 2556.87,4636.65 2556.87,4684.6 2551.6,4689.87
  region net SYSTEM_5V0: 4128.16,4421 4122.87,4415.71 4123.16,4415.43 4123.16,4367.52 4129.33,4361.35 4175.47,4361.35 4181.9,4367.78 4181.9,4415.73 4176.64,4421
  region net SYSTEM_3V3: 5428.5,5134.79 5423.08,5140.21 5375.13,5140.21 5369.76,5134.91 5369.76,5105.96 5375.02,5100.7 5423.5,5100.7 5428.78,5105.99 5428.5,5106.27
  region net 12XX_2_1V0_RF1_FILT: 4785.96,3522.44 4780.54,3527.86 4732.59,3527.86 4727.22,3522.56 4727.22,3493.62 4732.48,3488.36 4780.96,3488.36 4786.25,3493.64 4785.96,3493.93
  region net 12XX_2_1V0_RF2_FILT: 5238.93,2890.61 5244.61,2884.92 5272.41,2884.92 5278.44,2890.95 5278.44,2957.75 5273.13,2963.12 5244.19,2963.12 5238.93,2957.86
  region net 12XX_2_1V0_RF1_FILT: 5530.8,2067.9 5525.52,2062.62 5525.8,2062.33 5525.8,2014.43 5531.98,2008.25 5578.11,2008.25 5584.55,2014.69 5584.55,2062.64 5579.28,2067.9
  region net PMIC2_VIN_B3: 5338.43,1070.07 5333.25,1064.89 5287.55,1064.89 5282.54,1069.9 5282.54,1078.84 5324.94,1121.23 5332.95,1121.23 5338.43,1115.76
  region net PMIC2_VIN_B2: 5570.1,1070.07 5575.28,1064.89 5620.98,1064.89 5625.98,1069.9 5625.98,1078.84 5583.59,1121.23 5575.57,1121.23 5570.1,1115.76
  region net PMIC2_VIN_B0: 5570.1,880.14 5575.28,885.32 5620.98,885.32 5625.98,880.31 5625.98,871.38 5583.59,828.98 5575.57,828.98 5570.1,834.46
  region net PMIC2_VIN_B1: 5338.43,880.14 5333.25,885.32 5287.55,885.32 5282.54,880.31 5282.54,871.38 5324.94,828.98 5332.95,828.98 5338.43,834.46
  region net PMIC1_VIN_B3: 467.7,1857.93 462.53,1852.75 416.83,1852.75 411.82,1857.75 411.82,1866.69 454.22,1909.09 462.23,1909.09 467.7,1903.61
  region net PMIC1_VIN_B2: 699.37,1857.93 704.55,1852.75 750.25,1852.75 755.26,1857.75 755.26,1866.69 712.86,1909.09 704.85,1909.09 699.37,1903.61
  region net PMIC1_VIN_B0: 699.37,1668 704.55,1673.18 750.25,1673.18 755.26,1668.17 755.26,1659.23 712.86,1616.84 704.85,1616.84 699.37,1622.31
  region net PMIC1_VIN_B1: 467.7,1668 462.53,1673.18 416.83,1673.18 411.82,1668.17 411.82,1659.23 454.22,1616.84 462.23,1616.84 467.7,1622.31
  region net 12XX_2_1V0_RF1_FILT: 5805.08,436.36 5799.8,431.08 5800.08,430.8 5800.08,382.89 5806.26,376.72 5852.39,376.72 5858.82,383.15 5858.82,431.1 5853.56,436.36
  region net 12XX_2_1V0_RF2_FILT: 5774.35,579.38 5769.06,574.1 5769.34,573.81 5769.34,525.91 5775.52,519.73 5821.66,519.73 5828.09,526.16 5828.09,574.12 5822.82,579.38
  region net 12XX_1_1V0_RF2_FILT: 2761.15,1302.47 2761.15,1284.2 2767.54,1277.81 2794.49,1277.81 2800.93,1284.25 2800.93,1351 2795.01,1356.92 2766.59,1356.92 2761.14,1351.48 2761.14,1302.48
  region net 12XX_2_1V2_FILT: 4755.72,1315.7 4750.43,1310.42 4750.71,1310.13 4750.71,1262.23 4756.89,1256.05 4803.03,1256.05 4809.46,1262.48 4809.46,1310.44 4804.19,1315.7
  region net 12XX_3_1V8_FILT: 4929.6,1404.03 4924.32,1398.74 4924.6,1398.46 4924.6,1350.56 4930.78,1344.38 4976.91,1344.38 4983.34,1350.81 4983.34,1398.77 4978.08,1404.03
  region net SYSTEM_5V0: 3939.25,650.91 3988.25,650.91 3993.69,645.46 3993.69,617.04 3987.77,611.12 3939.96,611.12 3934.04,617.04 3934.04,645.7 3939.24,650.9
  region net SYSTEM_5V0: 3938.79,510.36 3987.79,510.36 3993.24,504.92 3993.24,476.5 3987.32,470.57 3939.51,470.57 3933.59,476.5 3933.59,505.16 3938.79,510.35
  region net GND: 4119.13,512.68 4123.93,507.89 4123.93,437.77 4118.78,432.62 4050.85,432.62 4043.44,440.03 4043.44,505.72 4050.4,512.68
  region net 12XX_3_1V2_FILT: 3927.84,1110.58 3933.19,1115.94 3982.82,1115.94 3987.48,1111.28 3987.48,1062.72 3981.35,1056.58 3934.18,1056.58 3927.84,1062.92
  region net 12XX_1_1V0_RF2_FILT: 1496.65,721.57 1496.65,676.41 1497.73,675.32 1504.94,668.12 1552.12,668.12 1558.09,674.09 1558.09,723.96 1553.52,728.53 1503.61,728.53
  pour cut-out: 5312.21,776.26 5312.21,740.08 5315.51,736.78 5394.92,736.78 5399.35,741.21 5399.35,776.68 5396.27,779.76 5315.72,779.76
  pour cut-out: 5508.99,776.26 5508.99,740.08 5512.29,736.78 5591.7,736.78 5596.13,741.21 5596.13,776.68 5593.05,779.76 5512.5,779.76
  pour cut-out: 5508.99,1209.18 5508.99,1173 5512.29,1169.71 5591.7,1169.71 5596.13,1174.14 5596.13,1209.61 5593.05,1212.69 5512.5,1212.69
  pour cut-out: 5312.21,1209.18 5312.21,1173 5315.51,1169.71 5394.92,1169.71 5399.35,1174.14 5399.35,1209.61 5396.27,1212.69 5315.72,1212.69
  pour cut-out: 638.27,1564.11 638.27,1527.93 641.57,1524.64 720.98,1524.64 725.41,1529.07 725.41,1564.54 722.33,1567.62 641.78,1567.62
  pour cut-out: 441.49,1564.11 441.49,1527.93 444.79,1524.64 524.19,1524.64 528.63,1529.07 528.63,1564.54 525.55,1567.62 444.99,1567.62
  pour cut-out: 441.49,1997.04 441.49,1960.86 444.79,1957.56 524.19,1957.56 528.63,1961.99 528.63,1997.46 525.55,2000.54 444.99,2000.54
  pour cut-out: 638.27,1997.04 638.27,1960.86 641.57,1957.56 720.98,1957.56 725.41,1961.99 725.41,1997.46 722.33,2000.54 641.78,2000.54
  pour cut-out: 1317.77,2696.74 1317.77,2690.42 1329.87,2690.53 1329.87,2711.78 1324,2711.78
  pour cut-out: 2192.66,2682.81 2186.34,2682.81 2186.45,2670.7 2207.7,2670.7 2207.7,2676.58
  pour cut-out: 2464.68,2700.17 2458.36,2700.17 2458.47,2688.06 2479.72,2688.06 2479.72,2693.94
  pour cut-out: 4510.66,2588.93 4504.34,2588.93 4504.45,2576.83 4525.7,2576.83 4525.7,2582.7
  region net SYSTEM_3V3: 215.58,674.66 215.58,627.6 222.37,620.82 269.86,620.82 274.57,625.52 274.57,676.3 270.08,680.79 221.71,680.79
  text "7" at 1253.45,6.63 h65
  text ".Layer_Name" at 445.07,-990.08 h60
L8 BOTTOM:
  region net SYSTEM_3V3: 4845.85,289.56 4894.85,289.56 4900.29,284.12 4900.29,255.7 4894.37,249.77 4846.56,249.77 4840.64,255.7 4840.64,284.36 4845.84,289.55
  region net SYSTEM_1V8: 662.48,4740.5 662.48,4789.5 667.93,4794.94 696.35,4794.94 702.27,4789.02 702.27,4741.22 696.35,4735.29 667.69,4735.29 662.49,4740.49
  region net SYSTEM_3V3: 5428.5,5134.79 5423.08,5140.21 5375.13,5140.21 5369.76,5134.91 5369.76,5105.96 5375.02,5100.7 5423.5,5100.7 5428.78,5105.99 5428.5,5106.27
  region net 12XX_2_1V0_RF1_FILT: 5530.8,2067.9 5525.52,2062.62 5525.8,2062.33 5525.8,2014.43 5531.98,2008.25 5578.11,2008.25 5584.55,2014.69 5584.55,2062.64 5579.28,2067.9
  region net 12XX_1_1V0_RF2_FILT: 2761.15,1302.47 2761.15,1284.2 2767.54,1277.81 2794.49,1277.81 2800.93,1284.25 2800.93,1351 2795.01,1356.92 2766.59,1356.92 2761.14,1351.48 2761.14,1302.48
  region net 12XX_2_1V2_FILT: 4755.72,1315.7 4750.43,1310.42 4750.71,1310.13 4750.71,1262.23 4756.89,1256.05 4803.03,1256.05 4809.46,1262.48 4809.46,1310.44 4804.19,1315.7
  region net 12XX_3_1V8_FILT: 4929.6,1404.03 4924.32,1398.74 4924.6,1398.46 4924.6,1350.56 4930.78,1344.38 4976.91,1344.38 4983.34,1350.81 4983.34,1398.77 4978.08,1404.03
  region net PMIC2_VIN_B3: 5376.31,1078.65 5362.2,1064.54 5284.85,1064.54 5281.38,1068 5281.38,1101.76 5301.75,1122.13 5387.72,1122.13 5390.67,1119.18 5419.81,1090.03 5419.81,1067.82 5419.81,1036.92 5409.97,1036.92 5409.97,1068.81 5400.13,1078.65
  region net PMIC2_VIN_B2: 5532.22,1078.65 5546.33,1064.54 5623.68,1064.54 5627.14,1068 5627.14,1101.76 5606.77,1122.13 5520.81,1122.13 5517.86,1119.18 5488.71,1090.03 5488.71,1067.82 5488.71,1036.92 5498.55,1036.92 5498.55,1068.81 5508.4,1078.65
  region net PMIC2_VIN_B1: 5376.31,871.56 5362.2,885.67 5284.85,885.67 5281.38,882.21 5281.38,848.45 5301.75,828.08 5387.72,828.08 5390.67,831.03 5419.81,860.18 5419.81,882.39 5419.81,913.3 5409.97,913.3 5409.97,881.41 5400.13,871.56
  region net PMIC2_VIN_B0: 5532.22,871.56 5546.33,885.67 5623.68,885.67 5627.14,882.21 5627.14,848.45 5606.77,828.08 5520.81,828.08 5517.86,831.03 5488.71,860.18 5488.71,882.39 5488.71,913.3 5498.55,913.3 5498.55,881.41 5508.4,871.56
  region net PMIC1_VIN_B0: 661.49,1659.42 675.6,1673.53 752.95,1673.53 756.42,1670.07 756.42,1636.31 736.05,1615.94 650.09,1615.94 647.13,1618.89 617.99,1648.04 617.99,1670.25 617.99,1701.15 627.83,1701.15 627.83,1669.26 637.67,1659.42
  region net PMIC1_VIN_B1: 505.58,1659.42 491.47,1673.53 414.12,1673.53 410.66,1670.07 410.66,1636.31 431.03,1615.94 516.99,1615.94 519.94,1618.89 549.09,1648.04 549.09,1670.25 549.09,1701.15 539.25,1701.15 539.25,1669.26 529.4,1659.42
  region net PMIC1_VIN_B2: 661.49,1866.51 675.6,1852.39 752.95,1852.39 756.42,1855.86 756.42,1889.62 736.05,1909.99 650.09,1909.99 647.13,1907.04 617.99,1877.89 617.99,1855.68 617.99,1824.77 627.83,1824.77 627.83,1856.66 637.67,1866.51
  region net LMK2_3V3: 2154.89,3736.2 2170.48,3736.2 2175.61,3741.33 2195.77,3741.33 2206.87,3730.22 2206.87,3701.21 2197.01,3691.35 2169.2,3718.7 2155.43,3718.7 2152.6,3721.53 2152.6,3734.44 2153.62,3735.46
  region net LMK2_3V3: 2151.79,3838.29 2168.55,3838.29 2185.31,3855.05 2279.32,3855.05 2286.21,3848.15 2286.21,3826.22 2283.75,3823.76 2203.3,3823.76 2197.87,3818.33 2162.76,3818.33 2154.63,3826.47
  region net LMK2_3V3: 1821.48,3755.71 1836.03,3770.26 1869.95,3770.26 1878.63,3761.58 1893.77,3761.58 1893.77,3744.42 1893.54,3744.19 1882.28,3744.19 1863.39,3725.29 1828.18,3725.29 1818.98,3734.49
  pour cut-out: 2722,872 2739.75,889.75 3772.26,889.75 3854,808 3854,754.07 3685.81,585.88 2935.28,585.88 2898.25,622.91 2818.97,622.91 2720.56,721.32 2720.56,870.31
  pour cut-out: 1003.42,3072.36 970.49,3039.43 970.49,3018.45 1003.69,3018.45 1020.95,3035.71 1020.95,3058.82 1018.03,3061.74
  region net PMIC1_VIN_B3: 505.58,1866.51 491.47,1852.39 414.12,1852.39 410.66,1855.86 410.66,1889.62 431.03,1909.99 516.99,1909.99 519.94,1907.04 549.09,1877.89 549.09,1855.68 549.09,1824.77 539.25,1824.77 539.25,1856.66 529.4,1866.51
  pour cut-out: 2538.46,3041.14 2516.96,3041.14 2511.19,3046.9 2511.19,3065.3 2520.14,3074.26 2587.03,3074.26 2592.26,3069.03 2592.26,3036.15 2596.06,3032.35 2547.25,3032.35
  region net GND: 2527.09,3068.09 2575.72,3068.09 2581.95,3061.86 2581.95,3042.83 2577.51,3038.4 2553.71,3038.4 2545.26,3046.84 2523.84,3046.84 2517.79,3052.9 2517.79,3060.58 2525.21,3068 2526.66,3068
  pour cut-out: 4856.46,2947.14 4834.96,2947.14 4829.19,2952.9 4829.19,2971.3 4838.14,2980.26 4905.03,2980.26 4910.26,2975.03 4910.26,2942.15 4914.06,2938.35 4865.25,2938.35
  pour cut-out: 3853.46,3041.14 3831.96,3041.14 3826.19,3046.9 3826.19,3065.3 3835.14,3074.26 3896.47,3074.26 3900.59,3070.13 3900.59,3032.35 3862.25,3032.35
  pour cut-out: 1365.35,2947.14 1346.96,2947.14 1341.19,2952.9 1341.19,2971.3 1350.14,2980.26 1409.93,2980.26 1415,2975.19 1415,2938.35 1374.15,2938.35
  region net GND: 4845.75,2974.75 4892.13,2974.75 4900.92,2965.95 4900.92,2947.22 4897.95,2944.25 4871,2944.25 4862.32,2952.93 4844.61,2952.93 4837.3,2960.24 4837.3,2968.24 4839.47,2970.41
  region net GND: 3842.05,3067.98 3888.48,3067.98 3890.4,3066.06 3890.4,3040.31 3889.15,3039.07 3867.92,3039.07 3859.22,3047.77 3842.28,3047.77 3834.6,3055.45
  region net GND: 1356.16,2972.6 1401.74,2972.6 1405.64,2968.7 1405.64,2945.67 1401.49,2941.53 1383.7,2941.53 1372.25,2952.98 1357.87,2952.98 1350.07,2960.78 1350.31,2961.03 1350.31,2968.46
  pour cut-out: 3643.19,4505.21 3624,4486.02 3624,4485.92 3663.48,4485.92 3665,4484.4
  text "8" at 1253.45,9.16 h65
  text ".Layer_Name" at 445.07,-990.08 h60

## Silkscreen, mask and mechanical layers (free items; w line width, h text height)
Top Overlay:
  circle w10: c2653.03,3214.87 r1.46
  circle w10: c4962.25,3174.79 r1.46
  circle w10: c3957.11,3272.93 r1.46
  circle w10: c1472.79,3163.76 r1.46
  circle w10: c2532.59,2676.81 r1.46
  circle w10: c3845.29,2701.94 r1.46
  lines w6: 423.04,1781.99 448.5,1781.99 459.36,1792.84 ; 707.72,1792.84 718.57,1781.99 744.04,1781.99 ; 2015.77,3320.92 2043.77,3320.92 ; 2332.34,4938.98 2332.34,4951.39 2342.34,4961.38 2507.13,4961.38 ; 3141.02,5026.48 3188.68,5026.48 3205.92,5043.72 ; 3321.38,3093.5 3328.89,3086 3352,3086 ; 3668.24,2669.54 3675.41,2662.38 3741.82,2662.38 ; 4253.97,1016.98 4468.56,1016.98 4483.38,1002.16 ; 4445.75,3005.98 4445.75,2981.4 4432.68,2968.33 4362.08,2968.33 4347.96,2982.45 4347.96,3242.88 4364.32,3259.24 4443.08,3259.24 4454.64,3247.68 4454.64,3104.4 ; 4748.36,1000.98 4759.62,1012.24 5025.79,1012.24 ; 4899.9,871.66 4923.88,871.66 5036.32,759.22 5162.34,759.22 5174.84,771.72 5174.84,792.62 ; 2757.71,3485.51 2859.11,3384.1 3057.1,3384.1 3091.09,3418.09 3091.09,3570.29 3044.01,3617.38 2788.24,3617.38 2757.71,3586.85 2757.71,3485.51
  lines w6.01: 426.48,1732.27 450.83,1732.27 458.48,1724.62 ; 712.07,1737.99 720.84,1746.76 745.04,1746.76 ; 944.93,2996.07 982.13,2996.07 ; 1588.31,2920.15 1615.44,2893.02 1615.44,2758.19 1608.54,2751.29 ; 1625.3,3265.7 1625.3,3335.38 ; 1700.48,3384.1 1672.91,3356.53 1672.91,3172.93 1714.14,3131.7 1818.56,3131.7 1820.77,3131.7 ; 2113.51,3089.5 2157.08,3089.5 ; 2362.29,2651.87 2367.65,2657.23 2439.92,2657.23 ; 2403.8,2681.69 2410.79,2674.7 2496.54,2674.7 2515.65,2693.81 2667,2693.81 2681.98,2678.83 ; 2782.25,3010.69 2821.68,2971.25 2821.68,2844.48 2809.07,2831.87 ; 2786.12,3188.29 2842.17,3188.29 2856.1,3202.22 ; 3388.4,5126.8 3395.26,5133.65 3461.14,5133.65 3467.51,5127.29 ; 3859.81,2776.51 3897.55,2776.51 3958.94,2715.13 4017.83,2715.13 4023.22,2709.74 ; 3990.71,2828.22 3990.71,2786.03 3994.09,2782.65 4070.23,2782.65 4083.47,2795.89 4083.47,2851.3 ; 4965.85,2874.04 4965.85,2814.9 4976.87,2803.88 4976.87,2663.86 5000.58,2640.15 5050.13,2640.15 5086.72,2676.74 ; 5075.6,3098.77 5179.97,3098.77 5190.57,3109.37 ; 5080.41,3214.2 5177.07,3214.2 5184.64,3214.2 5191.66,3207.18 ; 5179.7,3099.94 5180.5,3099.94 5197.24,3116.68 ; 5308.53,994.3 5323.35,994.3 5332.39,1003.34 ; 5308.93,959.38 5327.58,959.38 5336.62,950.34 ; 5578.93,951.25 5587.97,960.29 5611.69,960.29 ; 5579.33,1004.26 5588.37,995.22 5611.41,995.22 ; 3558.04,2536.69 3582.59,2512.13 3582.59,2409.62 3609.6,2382.62 3771.65,2382.62 3817.69,2428.65 3817.69,2545.28 3799.88,2563.08 3764.07,2563.08 3685.68,2641.48 3573.77,2641.48 3558.04,2625.75 3558.04,2536.69 ; 5611.27,2605.83 5636.26,2580.84 5816.72,2580.84 5841.1,2605.21 5841.1,2920.7 5815.33,2946.47 5629.38,2946.47 5611.27,2928.36 5611.27,2605.83
  lines w6.1: 1700.48,3384.1 1827.83,3384.1 1862.51,3349.43 1862.51,3172.05 1822.15,3131.7 1820.77,3131.7 ; 2283.74,4769.46 2283.74,4951.15 2324.41,4991.82 ; 2864.51,4820.27 2889.85,4794.93 2889.85,4733.89 ; 5370.26,2568.68 5370.26,2921.86 5393.9,2945.51 5557.86,2945.51 5575.15,2928.22 5575.15,2572.59 5548.93,2546.37 5392.57,2546.37 5370.26,2568.68
  text "NERROR" at 5864.56,3405.4 h30
  text "A" at 3065.94,3343.26 h30
  text "E" at 4474.86,3226.96 h30
  text "D" at 1790.88,3088.59 h30
  text "E" at 5482.95,2962.08 h30
  text "C" at 3964.79,2848.15 h30
  text "D" at 1582.53,2827.14 h30
  text "A" at 2836.26,2824.62 h30
  text "B" at 4992.45,2589.89 h35
  text "C" at 3520.57,2577.97 h30
  text "B" at 5697.65,2527.19 h35
  text "NRST1" at 5037.95,808.98 h30 r90
  text "NRST4" at 5085.36,807.09 h30 r90
  text "NRST2" at 5132.21,805.65 h30 r90
  text "NRST3" at 5180.48,806.13 h30 r90
  text "3.3V" at -89.1,447.91 h30
  text "5V" at 398.79,446.75 h30
  text "Power" at 372.34,407.16 h30
  text "Power" at -102.79,403.42 h30
  text "mmWave Cascade Radar EVM" at 1250,250 h60
  text "MMWCAS-RF-EVM" at 1250,150 h60
  text "PROC054 REV-C" at 1250,-25 h60
  text ".Layer_Name" at 446,-989.49 h60
Bottom Overlay:
  circle w6: c2669,1068.58 r9.34
  circle w6: c542.01,423.47 r18.82
  circle w6: c311.73,690.17 r3.11
  lines w6: 277.79,1624 313.68,1624 334.05,1644.36 334.05,1882.26 314.76,1901.55 282.07,1901.55 ; 306.13,2363.74 306.13,2425.26 324.51,2443.64 ; 387.94,1087.03 407.64,1106.72 407.64,1154.69 ; 554.57,2448.13 567.1,2435.6 567.1,2313.29 ; 557.32,1106.96 568.59,1118.23 568.59,1215.51 ; 589.57,1213.58 589.57,1112.55 597.03,1105.09 ; 599.98,2313.29 599.98,2435.6 615.99,2451.62 ; 728.79,1163.91 728.79,1104.24 741.36,1091.67 ; 781.78,2367.49 781.78,2425.26 797.16,2440.64 ; 893.97,1588.83 853.56,1588.83 827.28,1615.11 827.28,1823.54 855.21,1851.47 899.61,1851.47 ; 945.37,3105.47 945.37,3133.19 ; 1244.3,3248.17 1273.25,3219.22 1273.25,3098.6 1264.29,3089.64 1251.2,3089.64 ; 1761.06,3991.09 1734.25,4017.89 1734.25,4191.28 1764.41,4221.43 ; 2548.11,4730.46 2593.13,4685.44 2593.13,4604.4 2626.4,4571.13 ; 2565.68,3188.55 2565.68,3200.84 2590.26,3225.43 2604,3225.43 ; 2694.82,525.06 2694.82,280.21 2732.55,242.48 ; 2831.59,4587.45 2831.59,4719.36 2887.16,4774.93 ; 2885.56,5055.79 2885.56,5097.21 2912.65,5124.29 ; 3769.96,3065.21 3769.96,3053.01 3793.34,3029.63 3793.34,3013.36 3821.81,2984.89 3821.81,2970.65 ; 4026.92,4588.28 4089.13,4650.49 4365.73,4650.49 4462.49,4747.26 4462.49,4794.75 ; 4713.62,3065.03 4713.62,3192.47 4738.96,3217.81 ; 4842.66,3048.72 4851.93,3057.98 4864.15,3057.98 ; 5158.94,840.78 5180.79,840.78 5211.25,871.24 5211.25,1078.76 5185.39,1104.63 5165.84,1104.63 ; 5305.31,273.19 5290.29,288.21 5290.29,391.19 5335.88,436.78 ; 5556.28,1682.51 5565.47,1673.31 5565.47,1519.58 ; 5739.61,1639.65 5749.37,1629.89 5749.37,1587.18 ; 5740.64,800.12 5727.47,800.12 5707.94,819.65 5707.94,1039.67 5729.99,1061.73 5742.92,1061.73 ; 4738.96,3217.81 4738.96,3217.81 ; 1285.67,1325.88 1285.67,1823.89 1349.44,1887.66 1652.96,1887.66 1718.37,1822.25 1718.37,1312.82 1661.22,1255.67 1355.88,1255.67 1285.67,1325.88 ; 1777.23,1306.77 1777.23,1820.65 1842.9,1886.32 2171.26,1886.32 2241.86,1815.73 2241.86,1313.34 2181.11,1252.6 1831.41,1252.6 1777.23,1306.77 ; 2672.45,4449.66 ccw(c2663.12,4449.66) 2672.45,4449.66 ; 4238.74,-20.4 4238.74,443.63 4292.21,497.1 4581.95,497.1 4629.82,449.23 4629.82,-17.03 4587.28,-59.56 4277.91,-59.56 4238.74,-20.4 ; 5311.42,2160.49 5311.42,2563.21 5399.97,2651.75 5770.6,2651.75 5850.11,2572.24 5850.11,2160.49 5796.05,2106.43 5365.48,2106.43 5311.42,2160.49
  lines w6.01: 14.26,1984.82 27.03,1997.59 149.27,1997.59 176.03,1970.83 ; 2400.09,3410.53 2412.18,3398.44 2412.18,3210.34 2403.6,3201.75 ; 3631.92,3551.44 3622.87,3542.39 3622.87,3334.73 3640.89,3316.71 ; 4098.62,3221.52 4098.62,3304.76 ; 4873.32,1113.32 5013.68,1113.32 5046.66,1080.34 ; 5178.36,1577.17 5178.36,1648.9 5185.99,1656.54
  text "GND" at 5594.21,5071.21 h30
  text "GND" at 2288.75,5066.97 h30
  text "GND" at 570.04,5033.07 h30
  text "CONN_MONITOR_2" at 2473.41,4745.09 h35 r270
  text "4_PMIC_CLKOUT" at 3262.5,4696.64 h30
  text "3_DIG_SYNCOUT" at 3393.62,4647.48 h30 r270
  text "3_PMIC_CLKOUT" at 3502.68,4626.13 h30 r270
  text "4_DIG_SYNCOUT" at 2730.05,4612.04 h30 r270
  text "4_TDO" at 2622.58,4587.67 h35 r270
  text "3_TDO" at 3200.91,4495.54 h35 r270
  text "CONN_TP4" at 3547.79,3898.05 h35
  text "CONN_TP3" at 2991.13,3897.38 h35
  text "1_DIG_SYNCOUT" at 1680.5,3868.27 h30
  text "GND" at 188.34,3402.77 h30
  text "R" at 5601.76,2672.34 h30
  text "3_PMIC_CLKOUT" at 5815.62,2533.29 h30
  text "GND" at 6057.1,2437.86 h30
  text "PMIC2_TMPSNS_SCL" at 5819.52,2393.61 h30
  text "GND" at 1358.39,2324.2 h30
  text "PMIC2_TMPSNS_SDA" at 5819.66,2255.15 h30
  text "PMIC_BUCK_EN" at 5770.77,2131.18 h30
  text "Q" at 1507.19,1916.54 h30
  text "Q" at 315.74,1914.63 h30
  text "P" at 1886.62,1903.32 h30
  text "P" at 880.67,1866.26 h30
  text "PMIC_NRST" at 1656.03,1726.51 h30
  text "1_PMIC_CLKOUT" at 2195.12,1725.42 h30
  text "PMIC1_SCL" at 2135.41,1582.33 h30
  text "PMIC1_VANA" at 1673.26,1580.7 h30
  text "PMIC1_SDA" at 2142.9,1445.8 h30
  text "PMIC1_PGOOD" at 1666.63,1442.84 h30
  text "PMIC_BUCK_EN" at 2183.85,1304.05 h30
  text "PMIC1_GPIO2" at 1670.61,1302.33 h30
  text "CONN_TP1" at 3269.36,1205.83 h35
  text "CONN_TP2" at 3856.23,1181.59 h35
  text "CONN_MONITOR_1" at 2614.41,1146.35 h35
  text "GND" at 1346.62,1130.78 h30
  text "R" at 5753.36,1083.6 h30
  text "12XX_3_FMCW_CLKOUT" at 4728.12,1035.66 h30
  text "S" at 5257.82,988.51 h30
  text "2_TDO" at 3868.62,480.32 h35 r270
  text "1_TDO" at 3420.29,425.96 h35
  text "PMIC_NRST" at 4547.82,380.95 h30
  text "2_PMIC_CLKOUT" at 3700.98,357.6 h35
  text "2_DIG_SYNCOUT" at 4170.56,357.47 h35
  text "1_PMIC_CLKOUT" at 3155.4,352.81 h35
  text "GND" at 4778.55,318.04 h30
  text "PMIC2_VANA" at 4587.21,250.31 h30
  text "S" at 4678.84,211.3 h30
  text "PMIC2_PGOOD" at 4597.44,125.51 h30
  text "PMIC2_GPIO2" at 4593.35,-12.94 h30
  text ".Layer_Name" at 446,-989.49 h60
Top Paste:
  text ".Layer_Name" at 446,-989.49 h60
Bottom Paste:
  text ".Layer_Name" at 446,-989.49 h60
Top Solder:
  text ".Layer_Name" at 446,-989.49 h60
  text ".Layer_Name" at 446,-989.49 h60
Bottom Solder:
  text ".Layer_Name" at 446,-989.49 h60
Drill Guide:
  text ".Layer_Name" at 446,-989.49 h60
M1 Board Outline:
  the board outline again, w10
  text ".Layer_Name" at 445.07,-990.08 h60
M2 Board Dimensions:
  text ".Layer_Name" at 445.07,-990.08 h60
M3 3D STEP Top:
  text ".Layer_Name" at 446,-989.49 h60
M4 3D STEP Bottom:
  text ".Layer_Name" at 446,-989.49 h60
